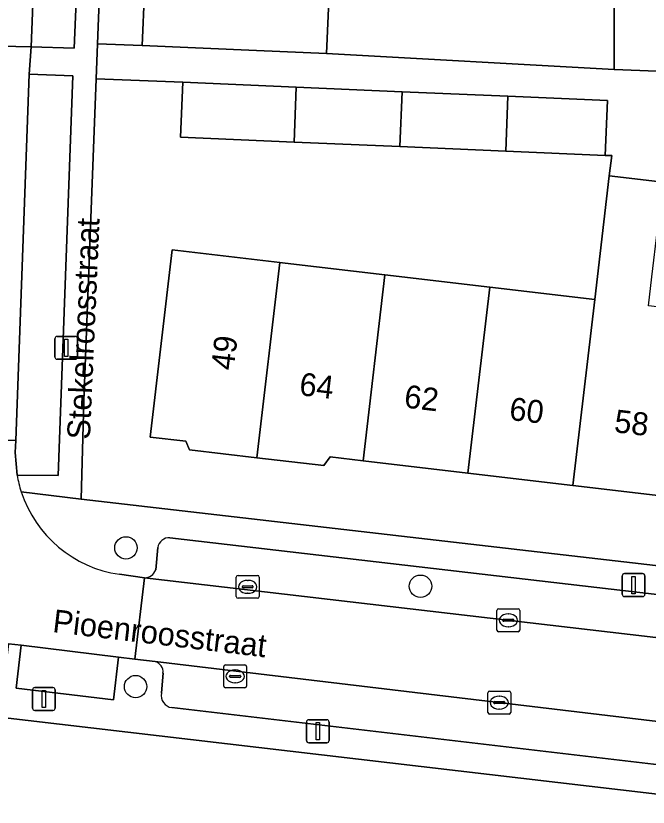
# Model space of a CAD drawing. Extents: x 162250 to 162661, y 380743 to 381606.
# Drawn here: x 162342.5 to 162370.1, y 380953.61 to 380988.14 of the extents above; entities that cross this region are included whole.
import ezdxf

# ---------------------------------------------------------------- set-up
doc = ezdxf.new("R2010")
doc.units = 0
for name, color, linetype in [('IMGEO_Boom', 7, 'Continuous'), ('IMGEO_Erf', 7, 'Continuous'), ('IMGEO_Kolk', 7, 'Continuous'), ('IMGEO_Lichtmast', 7, 'Continuous'), ('IMGEO_Openbare_ruimte_label', 7, 'Continuous'), ('IMGEO_Pand', 7, 'Continuous'), ('IMGEO_Pand_nummerreeks', 7, 'Continuous'), ('IMGEO_Parkeervlak_open', 7, 'Continuous'), ('IMGEO_Rijbaan_lokaal_open', 7, 'Continuous'), ('IMGEO_Voetpad_open', 7, 'Continuous')]:
    doc.layers.add(name, color=color, linetype=linetype)

msp = doc.modelspace()

# ---------------------------------------------------------------- linework, layer by layer
at = {"layer": 'IMGEO_Boom'}
for centre in [(162347.305, 380964.922), (162360.163, 380963.249), (162347.726, 380958.87)]:
    msp.add_circle(centre, 0.489, dxfattribs=at)
at = {"layer": 'IMGEO_Erf'}
for points in [[(162346.572, 381000), (162346.066, 380986.918), (162348.014, 380986.843), (162348.219, 380991.564)], [(162356.178, 380989.137), (162356.063, 380986.493), (162368.623, 380985.801), (162368.611, 380990.677)], [(162371.398, 380967.106), (162366.817, 380967.644), (162362.235, 380968.183), (162357.653, 380968.721), (162356.219, 380968.89), (162355.937, 380968.513), (162353.025, 380968.855), (162350.083, 380969.201), (162349.921, 380969.578), (162348.364, 380969.761), (162349.325, 380977.932), (162354.026, 380977.379), (162354.258, 380977.352), (162358.607, 380976.841), (162363.189, 380976.303), (162367.77, 380975.764), (162368.404, 380981.162), (162368.508, 380982.044), (162368.22, 380982.04), (162363.885, 380982.229), (162359.263, 380982.43), (162354.642, 380982.631), (162349.682, 380982.847), (162349.787, 380985.243), (162346.007, 380985.389), (162345.464, 380971.341), (162345.351, 380967.047), (162394.106, 380961.425)], [(162396.364, 380951.153), (162282.368, 380964.496)]]:
    msp.add_lwpolyline(points, dxfattribs=at)
at = {"layer": 'IMGEO_Kolk'}
for p, q in [((162352.196, 380963.724), (162353.048, 380963.724)), ((162352.121, 380962.798), (162352.121, 380963.65)), ((162352.609, 380963.504), (162352.634, 380963.504)), ((162353.122, 380963.65), (162353.122, 380962.798)), ((162352.38, 380963.218), (162352.38, 380963.23)), ((162352.818, 380963.181), (162352.42, 380963.181)), ((162352.423, 380963.267), (162352.821, 380963.267)), ((162352.864, 380963.23), (162352.864, 380963.218)), ((162353.048, 380962.724), (162352.196, 380962.724)), ((162352.632, 380962.944), (162352.607, 380962.944)), ((162363.497, 380961.339), (162363.497, 380962.191)), ((162363.572, 380962.265), (162364.424, 380962.265)), ((162363.985, 380962.045), (162364.01, 380962.045)), ((162364.498, 380962.191), (162364.498, 380961.339)), ((162363.756, 380961.759), (162363.756, 380961.771)), ((162364.194, 380961.722), (162363.796, 380961.722)), ((162363.799, 380961.808), (162364.197, 380961.808)), ((162364.24, 380961.771), (162364.24, 380961.759)), ((162364.008, 380961.485), (162363.983, 380961.485)), ((162364.424, 380961.265), (162363.572, 380961.265)), ((162351.571, 380958.892), (162351.571, 380959.744)), ((162351.646, 380959.818), (162352.498, 380959.818)), ((162352.059, 380959.598), (162352.084, 380959.598)), ((162352.572, 380959.744), (162352.572, 380958.892)), ((162351.83, 380959.312), (162351.83, 380959.324)), ((162352.268, 380959.275), (162351.87, 380959.275)), ((162351.873, 380959.361), (162352.271, 380959.361)), ((162352.314, 380959.324), (162352.314, 380959.312)), ((162352.082, 380959.038), (162352.057, 380959.038)), ((162352.498, 380958.818), (162351.646, 380958.818)), ((162363.101, 380957.747), (162363.101, 380958.599)), ((162363.176, 380958.673), (162364.028, 380958.673)), ((162364.102, 380958.599), (162364.102, 380957.747)), ((162363.36, 380958.167), (162363.36, 380958.179)), ((162363.403, 380958.216), (162363.801, 380958.216)), ((162363.589, 380958.453), (162363.614, 380958.453)), ((162363.844, 380958.179), (162363.844, 380958.167)), ((162363.798, 380958.13), (162363.4, 380958.13)), ((162363.612, 380957.893), (162363.587, 380957.893)), ((162364.028, 380957.673), (162363.176, 380957.673))]:
    msp.add_line(p, q, dxfattribs=at)
for points in [[(162352.196, 380963.724), (162353.048, 380963.724)], [(162352.121, 380962.798), (162352.121, 380963.65)], [(162353.122, 380963.65), (162353.122, 380962.798)], [(162353.048, 380962.724), (162352.196, 380962.724)], [(162363.497, 380961.339), (162363.497, 380962.191)], [(162363.572, 380962.265), (162364.424, 380962.265)], [(162364.498, 380962.191), (162364.498, 380961.339)], [(162364.424, 380961.265), (162363.572, 380961.265)], [(162351.571, 380958.892), (162351.571, 380959.744)], [(162351.646, 380959.818), (162352.498, 380959.818)], [(162352.572, 380959.744), (162352.572, 380958.892)], [(162352.498, 380958.818), (162351.646, 380958.818)], [(162363.101, 380957.747), (162363.101, 380958.599)], [(162363.176, 380958.673), (162364.028, 380958.673)], [(162364.102, 380958.599), (162364.102, 380957.747)], [(162364.028, 380957.673), (162363.176, 380957.673)]]:
    msp.add_lwpolyline(points, dxfattribs=at)
for centre, radius, start, end in [((162352.198, 380963.648), 0.0765, 91.552, 178.448), ((162352.198, 380963.648), 0.0765, 91.552, 178.448), ((162353.046, 380963.648), 0.0765, 1.552, 88.448), ((162353.046, 380963.648), 0.0765, 1.552, 88.448), ((162352.42, 380963.227), 0.0403, 85.8775, 175.7526), ((162352.417, 380963.217), 0.0366, 178.938, 274.7102), ((162352.821, 380963.224), 0.043, 264.8664, 352.4533), ((162352.825, 380963.229), 0.0386, 1.7309, 96.639), ((162352.198, 380962.8), 0.0765, 181.552, 268.448), ((162352.198, 380962.8), 0.0765, 181.552, 268.448), ((162353.046, 380962.8), 0.0765, 271.552, 358.448), ((162353.046, 380962.8), 0.0765, 271.552, 358.448), ((162363.574, 380962.189), 0.0765, 91.552, 178.448), ((162363.574, 380962.189), 0.0765, 91.552, 178.448), ((162364.422, 380962.189), 0.0765, 1.552, 88.448), ((162364.422, 380962.189), 0.0765, 1.552, 88.448), ((162363.796, 380961.768), 0.0403, 85.8775, 175.7526), ((162363.793, 380961.758), 0.0366, 178.938, 274.7102), ((162364.197, 380961.765), 0.043, 264.8664, 352.4533), ((162364.201, 380961.77), 0.0386, 1.7309, 96.639), ((162363.574, 380961.341), 0.0765, 181.552, 268.448), ((162363.574, 380961.341), 0.0765, 181.552, 268.448), ((162364.422, 380961.341), 0.0765, 271.552, 358.448), ((162364.422, 380961.341), 0.0765, 271.552, 358.448), ((162351.648, 380959.742), 0.0765, 91.552, 178.448), ((162351.648, 380959.742), 0.0765, 91.552, 178.448), ((162352.496, 380959.742), 0.0765, 1.552, 88.448), ((162352.496, 380959.742), 0.0765, 1.552, 88.448), ((162351.87, 380959.321), 0.0403, 85.8775, 175.7526), ((162351.867, 380959.311), 0.0366, 178.938, 274.7102), ((162352.271, 380959.318), 0.043, 264.8664, 352.4533), ((162352.275, 380959.323), 0.0386, 1.7309, 96.639), ((162351.648, 380958.894), 0.0765, 181.552, 268.448), ((162351.648, 380958.894), 0.0765, 181.552, 268.448), ((162352.496, 380958.894), 0.0765, 271.552, 358.448), ((162352.496, 380958.894), 0.0765, 271.552, 358.448), ((162363.178, 380958.597), 0.0765, 91.552, 178.448), ((162363.178, 380958.597), 0.0765, 91.552, 178.448), ((162364.026, 380958.597), 0.0765, 1.552, 88.448), ((162364.026, 380958.597), 0.0765, 1.552, 88.448), ((162363.4, 380958.176), 0.0403, 85.8775, 175.7526), ((162363.397, 380958.166), 0.0366, 178.938, 274.7102), ((162363.801, 380958.173), 0.043, 264.8664, 352.4533), ((162363.805, 380958.178), 0.0386, 1.7309, 96.639), ((162363.178, 380957.749), 0.0765, 181.552, 268.448), ((162363.178, 380957.749), 0.0765, 181.552, 268.448), ((162364.026, 380957.749), 0.0765, 271.552, 358.448), ((162364.026, 380957.749), 0.0765, 271.552, 358.448)]:
    msp.add_arc(centre, radius, start, end, dxfattribs=at)
for centre, major_axis, ratio, start_param, end_param in [((162352.608, 380963.224), (-0.387, 0.002), 0.722429, 4.712389, 7.853982), ((162352.633, 380963.224), (-0.39, 0.002), 0.717154, 1.570796, 4.712389), ((162363.984, 380961.765), (-0.387, 0.002), 0.722429, 4.712389, 7.853982), ((162364.009, 380961.765), (-0.39, 0.002), 0.717154, 1.570796, 4.712389), ((162352.058, 380959.318), (-0.387, 0.002), 0.722429, 4.712389, 7.853982), ((162352.083, 380959.318), (-0.39, 0.002), 0.717154, 1.570796, 4.712389), ((162363.588, 380958.173), (-0.387, 0.002), 0.722429, 4.712389, 7.853982), ((162363.613, 380958.173), (-0.39, 0.002), 0.717154, 1.570796, 4.712389)]:
    msp.add_ellipse(centre, major_axis=major_axis, ratio=ratio, start_param=start_param, end_param=end_param, dxfattribs=at)
at = {"layer": 'IMGEO_Lichtmast'}
for p, q in [((162344.203, 380973.25), (162344.203, 380974.05)), ((162344.203, 380974.05), (162344.203, 380973.25)), ((162344.303, 380974.15), (162345.093, 380974.15)), ((162345.093, 380974.15), (162344.303, 380974.15)), ((162345.193, 380974.05), (162345.193, 380973.25)), ((162345.193, 380973.25), (162345.193, 380974.05)), ((162345.093, 380973.15), (162344.303, 380973.15)), ((162344.303, 380973.15), (162345.093, 380973.15)), ((162368.965, 380962.899), (162368.965, 380963.699)), ((162368.965, 380963.699), (162368.965, 380962.899)), ((162369.065, 380963.799), (162369.855, 380963.799)), ((162369.855, 380963.799), (162369.065, 380963.799)), ((162369.955, 380963.699), (162369.955, 380962.899)), ((162369.955, 380962.899), (162369.955, 380963.699)), ((162369.855, 380962.799), (162369.065, 380962.799)), ((162369.065, 380962.799), (162369.855, 380962.799)), ((162343.225, 380957.931), (162343.225, 380958.731)), ((162343.225, 380958.731), (162343.225, 380957.931)), ((162343.325, 380958.831), (162344.115, 380958.831)), ((162344.115, 380958.831), (162343.325, 380958.831)), ((162344.215, 380958.731), (162344.215, 380957.931)), ((162344.215, 380957.931), (162344.215, 380958.731)), ((162344.115, 380957.831), (162343.325, 380957.831)), ((162343.325, 380957.831), (162344.115, 380957.831)), ((162355.184, 380956.524), (162355.184, 380957.324)), ((162355.184, 380957.324), (162355.184, 380956.524)), ((162355.284, 380957.424), (162356.074, 380957.424)), ((162356.074, 380957.424), (162355.284, 380957.424)), ((162356.174, 380957.324), (162356.174, 380956.524)), ((162356.174, 380956.524), (162356.174, 380957.324)), ((162356.074, 380956.424), (162355.284, 380956.424)), ((162355.284, 380956.424), (162356.074, 380956.424))]:
    msp.add_line(p, q, dxfattribs=at)
for points in [[(162344.623, 380974.025), (162344.773, 380974.025), (162344.773, 380973.275), (162344.623, 380973.275), (162344.623, 380974.025)], [(162369.385, 380963.674), (162369.535, 380963.674), (162369.535, 380962.924), (162369.385, 380962.924), (162369.385, 380963.674)], [(162343.645, 380958.706), (162343.795, 380958.706), (162343.795, 380957.956), (162343.645, 380957.956), (162343.645, 380958.706)], [(162355.604, 380957.299), (162355.754, 380957.299), (162355.754, 380956.549), (162355.604, 380956.549), (162355.604, 380957.299)]]:
    msp.add_lwpolyline(points, dxfattribs=at)
for centre, start, end in [((162344.303, 380974.05), 90, 180), ((162344.303, 380974.05), 90, 180), ((162345.093, 380974.05), 0, 90), ((162345.093, 380974.05), 360, 90), ((162344.303, 380973.25), 180, 270), ((162344.303, 380973.25), 180, 270), ((162345.093, 380973.25), 270, 0), ((162345.093, 380973.25), 270, 0), ((162369.065, 380963.699), 90, 180), ((162369.065, 380963.699), 90, 180), ((162369.855, 380963.699), 0, 90), ((162369.855, 380963.699), 360, 90), ((162369.065, 380962.899), 180, 270), ((162369.065, 380962.899), 180, 270), ((162369.855, 380962.899), 270, 0), ((162369.855, 380962.899), 270, 0), ((162343.325, 380958.731), 90, 180), ((162343.325, 380958.731), 90, 180), ((162344.115, 380958.731), 0, 90), ((162344.115, 380958.731), 360, 90), ((162343.325, 380957.931), 180, 270), ((162343.325, 380957.931), 180, 270), ((162344.115, 380957.931), 270, 0), ((162344.115, 380957.931), 270, 0), ((162355.284, 380957.324), 90, 180), ((162355.284, 380957.324), 90, 180), ((162356.074, 380957.324), 0, 90), ((162356.074, 380957.324), 360, 90), ((162355.284, 380956.524), 180, 270), ((162355.284, 380956.524), 180, 270), ((162356.074, 380956.524), 270, 0), ((162356.074, 380956.524), 270, 0)]:
    msp.add_arc(centre, 0.1, start, end, dxfattribs=at)
at = {"layer": 'IMGEO_Pand'}
for points in [[(162358.335, 380991.124), (162356.541, 380991.202), (162348.219, 380991.564), (162348.014, 380986.843), (162353.01, 380986.626), (162356.063, 380986.493), (162356.178, 380989.137), (162358.245, 380989.047)], [(162371.201, 380990.564), (162368.611, 380990.677), (162368.623, 380985.801), (162371.215, 380985.688)], [(162354.642, 380982.631), (162354.737, 380985.028), (162349.787, 380985.243), (162349.682, 380982.847)], [(162354.642, 380982.631), (162359.263, 380982.43), (162359.358, 380984.826), (162354.737, 380985.028)], [(162363.885, 380982.229), (162363.98, 380984.625), (162359.358, 380984.826), (162359.263, 380982.43)], [(162363.885, 380982.229), (162368.22, 380982.04), (162368.324, 380984.436), (162363.98, 380984.625)], [(162372.352, 380975.226), (162370.119, 380975.488), (162370.267, 380976.75), (162370.753, 380980.886), (162368.404, 380981.162), (162367.77, 380975.764), (162366.817, 380967.644), (162371.398, 380967.106)], [(162354.026, 380977.379), (162349.325, 380977.932), (162348.364, 380969.761), (162349.921, 380969.578), (162350.083, 380969.201), (162353.025, 380968.855)], [(162354.026, 380977.379), (162353.025, 380968.855), (162355.937, 380968.513), (162356.219, 380968.89), (162357.653, 380968.721), (162358.607, 380976.841), (162354.258, 380977.352)], [(162363.189, 380976.303), (162358.607, 380976.841), (162357.653, 380968.721), (162362.235, 380968.183)], [(162363.189, 380976.303), (162362.235, 380968.183), (162366.817, 380967.644), (162367.77, 380975.764)]]:
    msp.add_lwpolyline(points, close=True, dxfattribs=at)
at = {"layer": 'IMGEO_Parkeervlak_open'}
for points in [[(162343.397, 380992.747), (162343.163, 380986.78), (162345.037, 380986.723), (162345.325, 380993.244), (162345.435, 380997.681), (162343.619, 380997.747)], [(162344.989, 380985.516), (162343.084, 380985.588), (162342.495, 380969.61), (162342.476, 380969.092), (162342.553, 380968.091), (162344.349, 380968.083)], [(162342.735, 380960.674), (162342.509, 380958.81), (162346.756, 380958.297), (162346.981, 380960.157)]]:
    msp.add_lwpolyline(points, close=True, dxfattribs=at)
for points in [[(162391.121, 380960.493), (162349.221, 380965.369)], [(162348.693, 380964.938), (162348.602, 380963.971)], [(162348.113, 380963.62), (162391.637, 380958.538), (162391.432, 380959.016), (162391.546, 380959.968)], [(162391.241, 380954.88), (162348.578, 380959.963)], [(162348.922, 380959.465), (162348.857, 380958.585)], [(162349.301, 380957.956), (162390.118, 380953.163)]]:
    msp.add_lwpolyline(points, dxfattribs=at)
for centre, radius, start, end in [((162349.206, 380964.848), 0.521, 88.3781, 170.0706), ((162348.117, 380964.131), 0.511, 269.5588, 341.7822), ((162348.455, 380959.51), 0.469, 354.4577, 74.8128), ((162349.368, 380958.475), 0.523, 167.822, 262.6132)]:
    msp.add_arc(centre, radius, start, end, dxfattribs=at)
at = {"layer": 'IMGEO_Rijbaan_lokaal_open'}
for points in [[(162339.157, 380988.064), (162339.119, 380986.868), (162343.163, 380986.78), (162343.397, 380992.747), (162339.37, 380992.927)], [(162343.084, 380985.588), (162343.163, 380986.78), (162339.119, 380986.868), (162339.037, 380985.062), (162338.509, 380972.948), (162338.492, 380969.758), (162342.495, 380969.61)], [(162391.637, 380958.538), (162348.113, 380963.62), (162347.688, 380960.071), (162348.578, 380959.963), (162391.241, 380954.88)]]:
    msp.add_lwpolyline(points, close=True, dxfattribs=at)
for points in [[(162342.553, 380968.091), (162342.476, 380969.092), (162342.495, 380969.61), (162338.492, 380969.758)], [(162333.779, 380965.354), (162332.699, 380965.436), (162332.355, 380965.483), (162331.977, 380961.942), (162332.589, 380961.89), (162337.083, 380961.332), (162337.683, 380961.253), (162342.172, 380960.742), (162342.735, 380960.674), (162346.981, 380960.157), (162347.688, 380960.071), (162348.113, 380963.62), (162347.022, 380963.772)]]:
    msp.add_lwpolyline(points, dxfattribs=at)
for centre, radius, start, end in [((162347.8, 380969.025), 5.33, 190.0934, 198.0912), ((162347.772, 380969.02), 5.302, 198.1369, 261.864)]:
    msp.add_arc(centre, radius, start, end, dxfattribs=at)
at = {"layer": 'IMGEO_Voetpad_open'}
for points in [[(162350.27, 381109.922), (162349.753, 381098.417), (162349.681, 381096.654), (162348.578, 381072.082), (162348.521, 381070.283), (162347.574, 381047.676), (162347.499, 381045.78), (162346.542, 381023.306), (162346.446, 381021.366), (162346.026, 381009.859), (162345.558, 380999.659), (162345.435, 380997.681), (162345.325, 380993.244), (162345.037, 380986.723), (162343.163, 380986.78), (162343.084, 380985.588), (162344.989, 380985.516), (162344.349, 380968.083), (162342.553, 380968.091)], [(162342.734, 380967.37), (162345.351, 380967.047), (162345.464, 380971.341), (162346.007, 380985.389), (162346.066, 380986.918), (162346.572, 381000), (162348.851, 381051.523)], [(162371.215, 380985.688), (162368.623, 380985.801), (162356.063, 380986.493), (162353.01, 380986.626), (162348.014, 380986.843), (162346.066, 380986.918), (162346.007, 380985.389), (162349.787, 380985.243), (162354.737, 380985.028), (162359.358, 380984.826), (162363.98, 380984.625), (162368.324, 380984.436), (162368.22, 380982.04), (162368.508, 380982.044), (162368.404, 380981.162), (162370.753, 380980.886)], [(162284.836, 380967.471), (162283.759, 380967.586), (162282.665, 380967.703), (162282.368, 380964.496), (162396.364, 380951.153)], [(162345.351, 380967.047), (162342.734, 380967.37)], [(162400.509, 380962.127), (162400.689, 380963.562), (162400.114, 380962.988), (162398.044, 380960.92), (162396.035, 380961.166), (162394.106, 380961.425), (162345.351, 380967.047)], [(162349.221, 380965.369), (162391.121, 380960.493)], [(162348.602, 380963.971), (162348.693, 380964.938)], [(162347.022, 380963.772), (162348.113, 380963.62)], [(162348.578, 380959.963), (162347.688, 380960.071), (162346.981, 380960.157), (162346.756, 380958.297), (162342.509, 380958.81), (162342.735, 380960.674), (162342.172, 380960.742), (162341.953, 380958.882), (162337.463, 380959.389), (162337.683, 380961.253), (162337.083, 380961.332), (162336.845, 380959.473), (162332.373, 380959.999), (162332.589, 380961.89), (162331.977, 380961.942), (162330.529, 380962.093)], [(162348.857, 380958.585), (162348.922, 380959.465)], [(162390.118, 380953.163), (162349.301, 380957.956)]]:
    msp.add_lwpolyline(points, dxfattribs=at)
for centre, radius, start, end in [((162347.8, 380969.025), 5.33, 190.0934, 198.0912), ((162347.772, 380969.02), 5.302, 198.1369, 261.864), ((162349.206, 380964.848), 0.521, 88.3781, 170.0706), ((162348.117, 380964.131), 0.511, 269.5588, 341.7822), ((162348.455, 380959.51), 0.469, 354.4577, 74.8128), ((162349.368, 380958.475), 0.523, 167.822, 262.6132)]:
    msp.add_arc(centre, radius, start, end, dxfattribs=at)

# ---------------------------------------------------------------- texts
at = {"layer": 'IMGEO_Openbare_ruimte_label'}
for s, rotation, p in [('Stekelroosstraat', 87.4781, (162345.73, 380969.634)), ('Pioenroosstraat', 353.2232, (162344.07, 380961.253))]:
    msp.add_text(s, height=1, rotation=rotation, dxfattribs=at).set_placement(p)
at = {"layer": 'IMGEO_Pand_nummerreeks'}
for s, rotation, p in [('49', 83.2922, (162352.006, 380972.643)), ('64', 353.2961, (162354.837, 380971.59)), ('62', 353.2961, (162359.415, 380971.051)), ('60', 353.2961, (162364.002, 380970.512)), ('58', 353.2964, (162368.583, 380969.974))]:
    msp.add_text(s, height=1, rotation=rotation, dxfattribs=at).set_placement(p)

doc.saveas('drawing.dxf')
